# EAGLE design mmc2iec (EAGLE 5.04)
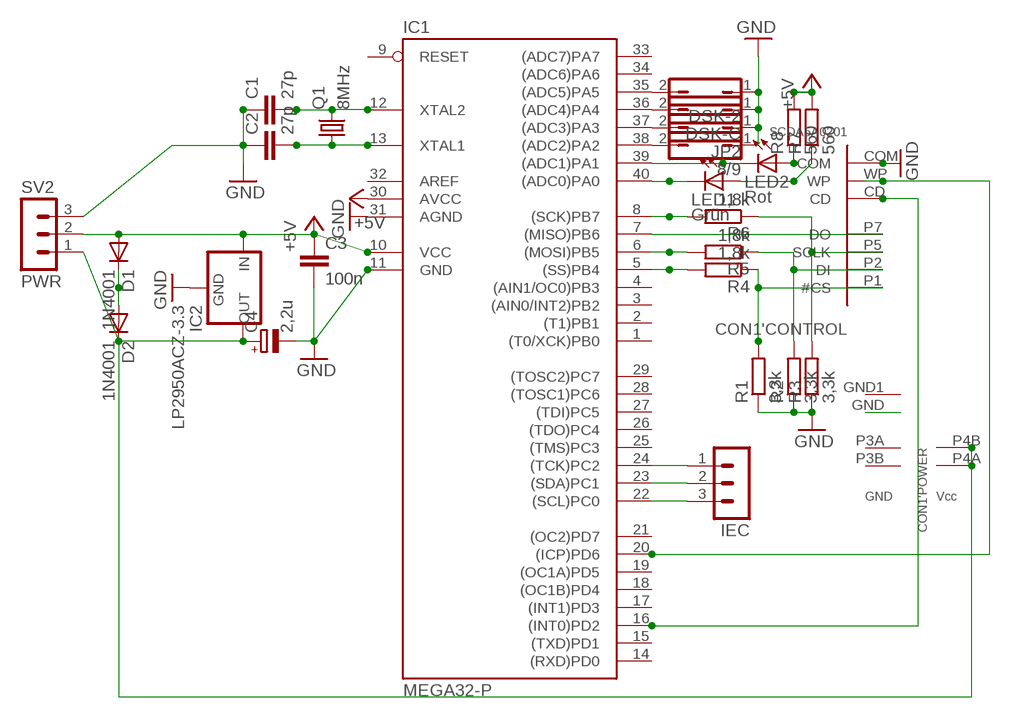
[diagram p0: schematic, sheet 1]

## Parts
8/9  JP1Q  [JP1]
C1  27p  C-EU025-025X050  [C025-025X050]
C2  27p  C-EU025-025X050  [C025-025X050]
C3  100n  C-EU025-025X050  [C025-025X050]
C4  2,2u  CPOL-EUE2.5-5  [E2,5-5]
CON1  SCDA5A0201  [SCDA5A0201]
D1  1N4001  1N4004  [DO41-10]
D2  1N4001  1N4004  [DO41-10]
DSK-2  JP1Q  [JP1]
DSK-C  JP1Q  [JP1]
IC1  MEGA32-P  [DIL40]
IC2  LP2950ACZ-3.3  [TO92]
IEC  MA03-1  [MA03-1]
JP2  JP1Q  [JP1]
LED1  Grün  LED3MM  [LED3MM]
LED2  Rot  LED3MM  [LED3MM]
Q1  8MHz  CRYSTALHC49U-V  [HC49U-V]
R1  3,3k  R-EU_0207/7  [0207/7]
R2  3,3k  R-EU_0207/7  [0207/7]
R3  3,3k  R-EU_0207/7  [0207/7]
R4  1,8k  R-EU_0207/7  [0207/7]
R5  1,8k  R-EU_0207/7  [0207/7]
R6  1,8k  R-EU_0207/7  [0207/7]
R7  560  R-EU_0207/7  [0207/7]
R8  560  R-EU_0207/7  [0207/7]
SV2  PWR  MA03-1  [MA03-1]

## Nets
+5V: C3.1 D1.A IC1.10(VCC) IC1.30(AVCC) IC2.3(IN) R7.2 R8.2 SV2.2
GND: 8/9.1 C1.1 C2.1 C3.2 C4.- CON1.COM('CONTROL:COM) DSK-2.1 DSK-C.1 IC1.11(GND) IC1.31(AGND) IC2.2(GND) JP2.1 R1.1 R2.1 R3.1 SV2.3
N$1: C1.2 IC1.12(XTAL2) Q1.2
N$2: C2.2 IC1.13(XTAL1) Q1.1
N$3: 8/9.2 IC1.38((ADC2)PA2)
N$4: IC1.5((SS)PB4) R4.2
N$5: IC1.6((MOSI)PB5) R5.2
N$6: IC1.8((SCK)PB7) R6.2
N$7: CON1.P1('CONTROL:#CS) R1.2 R4.1
N$8: CON1.P7('CONTROL:DO) IC1.7((MISO)PB6)
N$9: CON1.P2('CONTROL:DI) R2.2 R5.1
N$10: IC1.40((ADC0)PA0) LED1.K(C)
N$11: IC1.39((ADC1)PA1) LED2.K(C)
N$12: LED1.A R7.1
N$13: LED2.A R8.1
N$14: IC1.37((ADC3)PA3) JP2.2
N$15: C4.+ CON1.P4A('POWER:VCC) CON1.P4B('POWER:VCC1) D2.C IC2.1(OUT) SV2.1
N$16: D1.C D2.A
N$17: IC1.22((SCL)PC0) IEC.3
N$18: IC1.23((SDA)PC1) IEC.2
N$19: IC1.24((TCK)PC2) IEC.1
N$20: CON1.P5('CONTROL:SCLK) R3.2 R6.1
N$22: DSK-C.2 IC1.36((ADC4)PA4)
N$23: CON1.CD('CONTROL:CD) IC1.16((INT0)PD2)
N$24: CON1.WP('CONTROL:WP) IC1.20((ICP)PD6)
N$25: DSK-2.2 IC1.35((ADC5)PA5)
Unconnected: IC1.1((T0/XCK)PB0) IC1.2((T1)PB1) IC1.3((AIN0/INT2)PB2) IC1.4((AIN1/OC0)PB3) IC1.9(RESET) IC1.14((RXD)PD0) IC1.15((TXD)PD1) IC1.17((INT1)PD3) IC1.18((OC1B)PD4) IC1.19((OC1A)PD5) IC1.21((OC2)PD7) IC1.25((TMS)PC3) IC1.26((TDO)PC4) IC1.27((TDI)PC5) IC1.28((TOSC1)PC6) IC1.29((TOSC2)PC7) IC1.32(AREF) IC1.33((ADC7)PA7) IC1.34((ADC6)PA6)

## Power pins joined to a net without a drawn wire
GND: CON1.GND1('POWER:GND) CON1.GND('POWER:GND) CON1.P3A('POWER:GND) CON1.P3B('POWER:GND)

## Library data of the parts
8/9 DSK-2 DSK-C JP2 = jumper:JP1Q: JUMPER
C1-C3 = rcl:C-EU: CAPACITOR, European symbol
C4 = rcl:CPOL-EU: POLARIZED CAPACITOR, European symbol
CON1 = SCDA5A0201:SCDA5A0201: ALPS Connector for SDMemory Card SD-CARD SCDA5A0201 SPI -MODE
D1 D2 = diode:1N4004: DIODE
IC1 = atmel:MEGA32-P: MICROCONTROLLER 32 Kbytes FLASH 2 Kbytes SRAM 1 Kbytes EEPROM USART 8-channel 10 bit ADC Source: www.atmel.com .. doc2503.pdf
IC2 = v-reg:LP2950?*: Source: http://cache.national.com/ds/LP/LP2950.pdf
IEC SV2 = con-lstb:MA03-1: PIN HEADER
LED1 LED2 = led:LED: LED
Q1 = crystal:CRYSTAL: CRYSTAL
R1-R8 = rcl:R-EU_: RESISTOR, European symbol

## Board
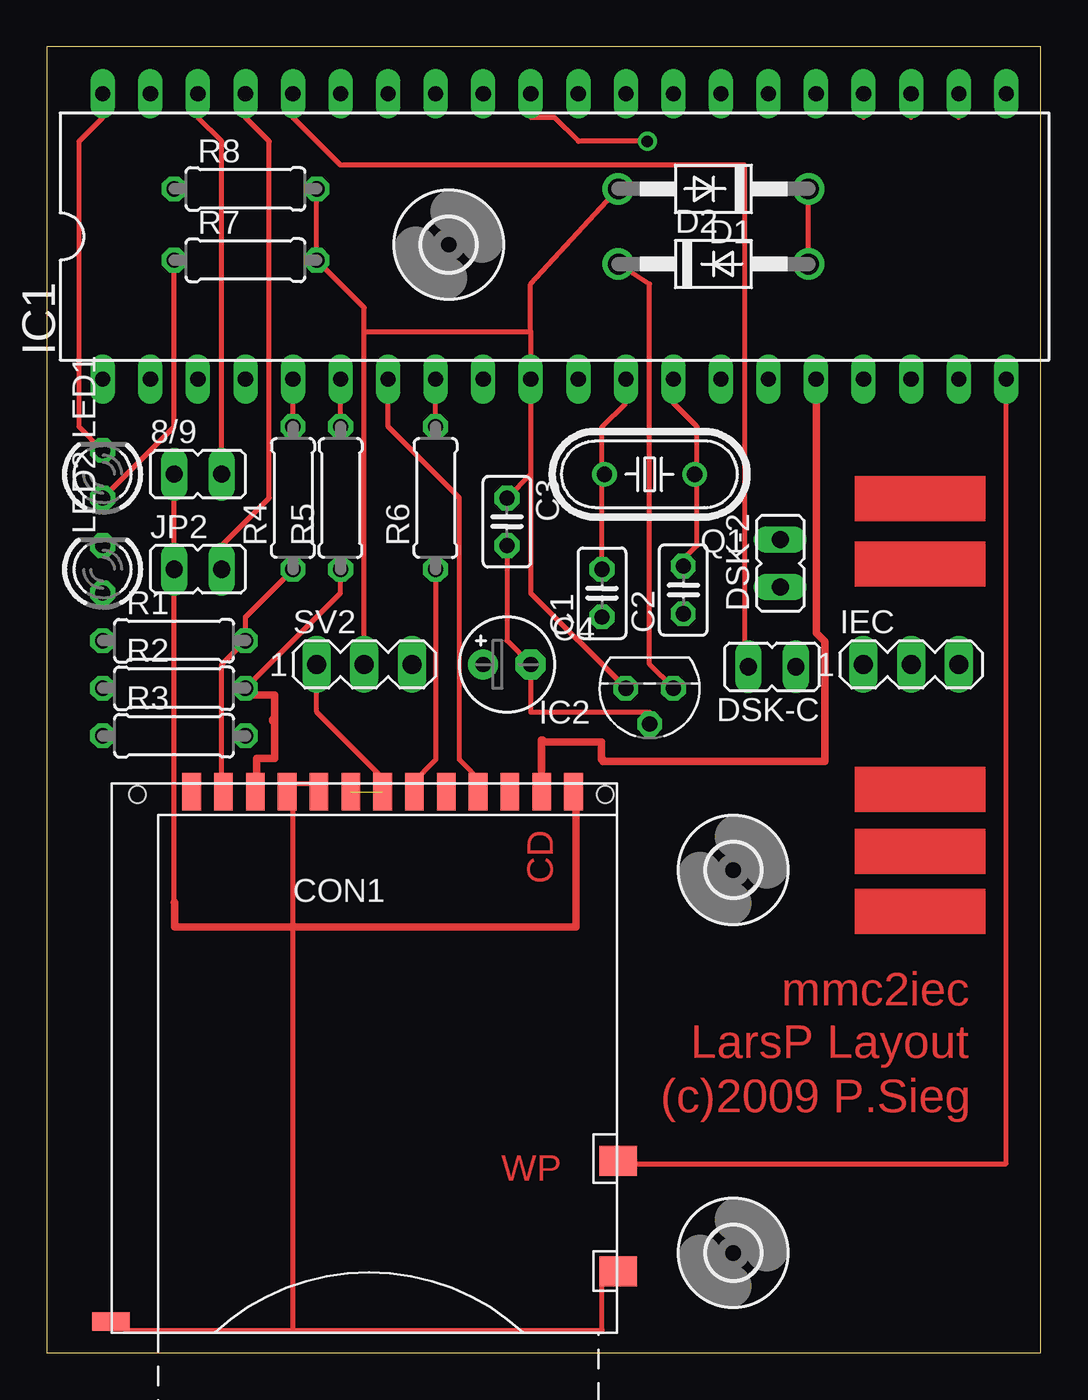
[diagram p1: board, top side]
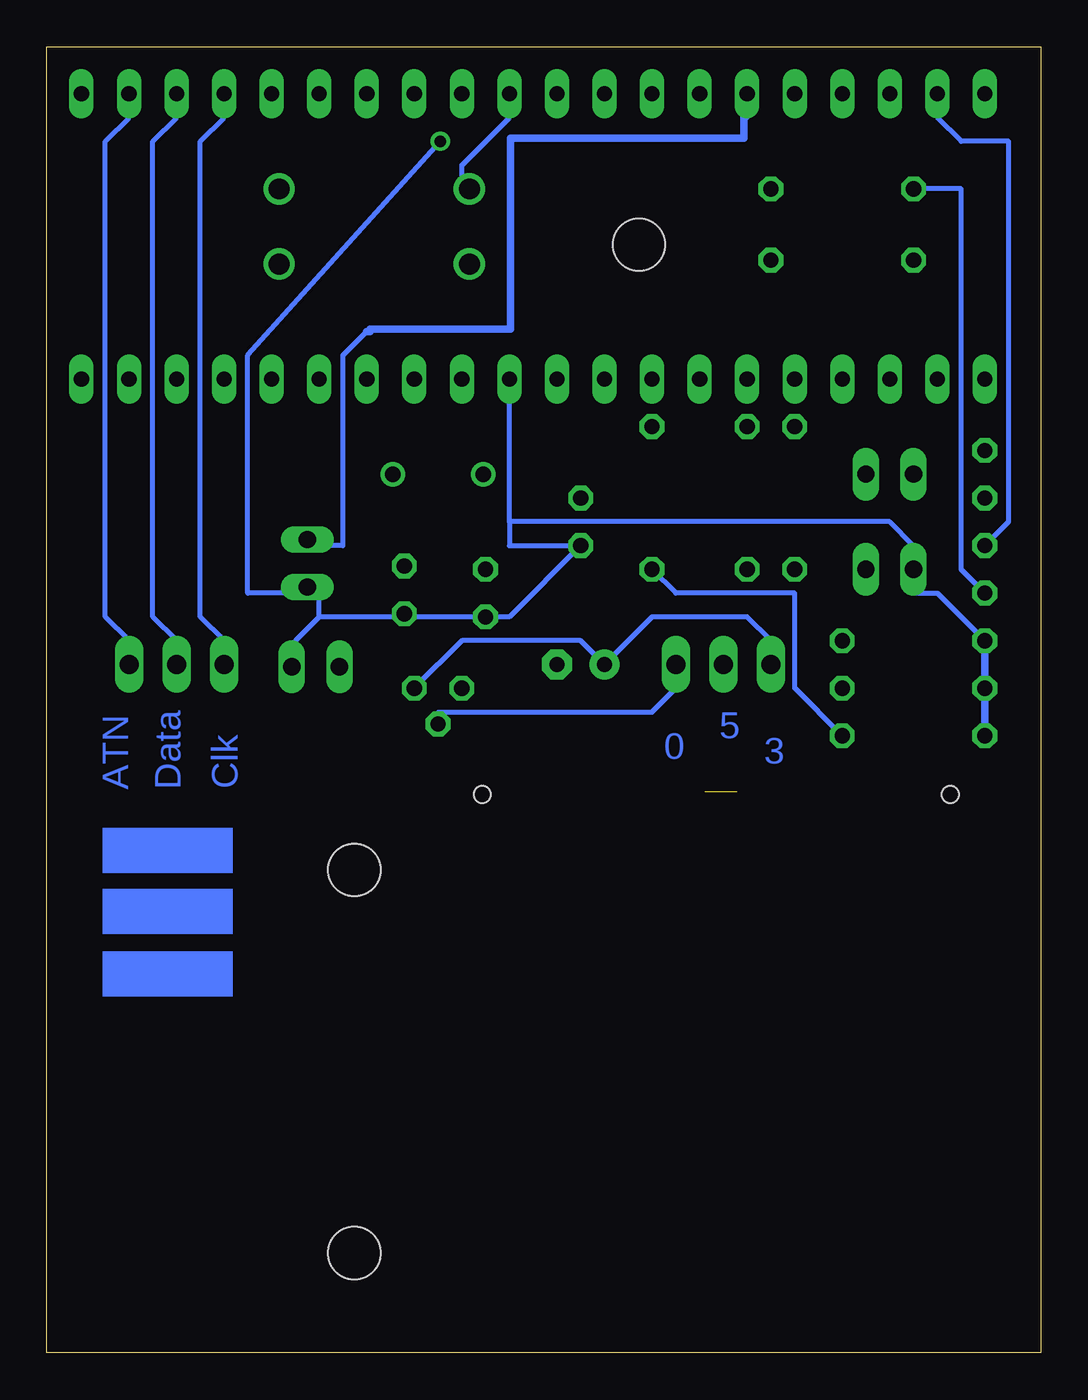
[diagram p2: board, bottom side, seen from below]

Size 53.1 x 69.75 mm. Coordinates in mm from the lower left corner, seen from the top.
Outline: 0,0 53.1,0 53.1,69.75 0,69.75 0,0
Copper layers (1*16): Top 0.035mm / dielectric 1.5mm / Bottom 0.035mm
Design rules "default": minimum track width 10mil, minimum drill 24mil, track to track 8mil, track to pad 8mil, pad to pad 8mil, via to via 8mil, smd to smd 8mil, copper to edge 40mil, drill to drill 8mil, minimum pad ring 10mil, minimum via ring 8mil, stop-mask expansion 4mil, vias tented up to drill 0mil, thermal gap 10mil

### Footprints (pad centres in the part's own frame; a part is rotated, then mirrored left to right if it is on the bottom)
JP1 = drill 0.914 long: 1 0,-1.27; 2 0,1.27
C025-025X050 = drill 0.813 octagon: 1 -1.27,0; 2 1.27,0
E2,5-5 = drill 0.813 pad 1.6 round: + -1.27,0 | drill 0.813 pad 1.6 octagon: - 1.27,0
SCDA5A0201 = smd 1 x 2: CD 9.475,-0.45; COM 11.175,-0.45; P1 -7.525,-0.45; P2 -5.825,-0.45; P3A -4.125,-0.45; P3B -2.425,-0.45; P4A -0.725,-0.45; P4B 0.975,-0.45; P5 2.675,-0.45; P6 4.375,-0.45; P7 6.075,-0.45; P8 7.775,-0.45; P9 -9.225,-0.45 | smd 2 x 1.6: GND 13.575,-26.05; WP 13.575,-20.15 | smd 2 x 1: GND1 -13.525,-28.75 | hole 0.9: -12.125,-0.6; 12.875,-0.6
DO41-10 = drill 1.118 round: A 5.08,0; C -5.08,0
DIL40 = drill 0.813 long: 1 -24.13,-7.62; 2 -21.59,-7.62; 3 -19.05,-7.62; 4 -16.51,-7.62; 5 -13.97,-7.62; 6 -11.43,-7.62; 7 -8.89,-7.62; 8 -6.35,-7.62; 9 -3.81,-7.62; 10 -1.27,-7.62; 11 1.27,-7.62; 12 3.81,-7.62; 13 6.35,-7.62; 14 8.89,-7.62; 15 11.43,-7.62; 16 13.97,-7.62; 17 16.51,-7.62; 18 19.05,-7.62; 19 21.59,-7.62; 20 24.13,-7.62; 21 24.13,7.62; 22 21.59,7.62; 23 19.05,7.62; 24 16.51,7.62; 25 13.97,7.62; 26 11.43,7.62; 27 8.89,7.62; 28 6.35,7.62; 29 3.81,7.62; 30 1.27,7.62; 31 -1.27,7.62; 32 -3.81,7.62; 33 -6.35,7.62; 34 -8.89,7.62; 35 -11.43,7.62; 36 -13.97,7.62; 37 -16.51,7.62; 38 -19.05,7.62; 39 -21.59,7.62; 40 -24.13,7.62
TO92 = drill 0.813 octagon: 1 -1.27,0; 2 0,1.905; 3 1.27,0
MA03-1 = drill 1.016 long: 1 -2.54,0; 2 0,0; 3 2.54,0
LED3MM = drill 0.813 octagon: A -1.27,0; K 1.27,0
HC49U-V = drill 0.813 round: 1 -2.413,0; 2 2.413,0
0207/7 = drill 0.813 octagon: 1 -3.81,0; 2 3.81,0
2,8 = hole 2.8: 0,0

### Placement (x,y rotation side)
8/9  8.07,46.92 270 top
C1  29.66,40.57 90 top
C2  34,40.74 90 top
C3  24.58,44.38 270 top
C4  24.58,36.76 0 top
CON1  16.96,30.41 0 top
D1  35.61,62.16 180 top
D2  35.61,58.15 0 top
DSK-2  39.18,42.16 0 top
DSK-C  38.74,36.64 90 top
IC1  27.12,59.62 0 top
IC2  32.2,35.49 180 top
IEC  46.17,36.76 0 top
JP2  8.07,41.84 270 top
LED1  2.99,46.92 90 top
LED2  2.99,41.84 90 top
Q1  32.2,46.92 180 top
R1  6.8,38.03 0 top
R2  6.8,35.49 0 top
R3  6.8,32.95 0 top
R4  13.15,45.65 90 top
R5  15.69,45.65 90 top
R6  20.77,45.65 90 top
R7  10.61,58.35 0 top
R8  10.61,62.16 0 top
SV2  16.96,36.76 0 top
U$1  [2,8]  36.67,25.78 0 top
U$2  [2,8]  21.47,59.18 0 top
U$3  [2,8]  36.67,5.33 0 top

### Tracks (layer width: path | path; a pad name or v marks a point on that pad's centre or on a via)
+5V
  Top 0.254: R8.2 R7.2 16.96,55.81 16.96,54.54 | SV2.2 16.96,54.54 | 25.85,46.92 C3.1 | 25.85,46.92 IC1.10 25.85,54.54 | IC2.3 25.85,40.57 25.85,46.92 | D1.A 25.85,57.08 25.85,54.54 | 16.96,54.54 25.85,54.54
  Bottom 0.254: IC1.30 28.39,65.97 30.93,63.43 30.93,62.16 D1.A
GND  (via drill 0.61)
  Top 0.254: CON1.P3B 14.42,30.41 13.15,30.41 CON1.P3A 13.15,29.14 13.15,22.73 13.15,1.2 | 13.15,1.2 29.66,1.2 29.66,3.74 CON1.GND | 13.15,1.2 4.26,1.2 CON1.GND1 | 8/9.1 JP2.1 6.8,24.06 | IC2.2 32.2,34.22 25.85,34.22 C4.- 24.58,38.03 C3.2 | v32.08,64.7 28.39,64.7 27.12,65.97 25.85,65.97 IC1.31
  Top 0.406: CON1.COM 28.27,29.96 28.27,22.73 13.15,22.73 6.82,22.73 6.82,24.06 6.8,24.06
  Bottom 0.254: R1.1 5.53,40.57 6.8,40.57 JP2.1 6.8,43.11 8.07,44.38 28.39,44.38 | SV2.3 19.5,35.49 20.77,34.22 32.2,34.22 IC2.2 | 28.39,44.38 28.39,43.11 C3.2 28.39,39.3 C1.1 33.47,39.3 | 28.39,44.38 IC1.11 | 38.55,39.3 39.82,38.03 DSK-C.1 | 33.47,39.3 38.55,39.3 | 33.47,39.3 C2.1 | 38.55,39.3 38.55,40.57 DSK-2.1 39.82,40.57 42.36,40.57 42.36,53.27 v32.08,64.7
  Bottom 0.406: R1.1 R2.1 2.99,32.53 3.02,32.53 3.02,32.83 | R3.1 3.02,32.95 3.02,32.83 | 3.02,32.73 3.02,32.83
N$1
  Top 0.254: C1.2 29.66,46.92 | 29.66,46.92 29.66,49.46 30.93,50.73 IC1.12 | 29.66,46.92 Q1.2
N$2
  Top 0.254: 34.74,46.92 34.74,49.46 33.47,50.73 IC1.13 | 34.74,46.92 34.74,43.11 33.47,41.84 C2.2 | 34.74,46.92 Q1.1
N$3
  Top 0.254: IC1.38 8.07,65.97 9.34,64.7 8/9.2
N$4
  Top 0.254: R4.2 IC1.5
N$5
  Top 0.254: R5.2 IC1.6
N$6
  Top 0.254: R6.2 IC1.8
N$7
  Top 0.254: CON1.P1 9.34,30.41 9.34,36.76 R1.2 10.61,39.3 R4.1
N$8
  Top 0.254: CON1.P7 23.31,30.41 22.04,31.68 22.04,45.65 18.23,49.46 IC1.7
N$9
  Top 0.254: R2.2 15.69,40.57 R5.1
  Top 0.406: 11.07,29.96 CON1.P2 11.22,29.96 11.22,31.73 12.17,31.73 12.17,33.28 | R2.2 10.77,35.49 10.77,35.13 12.17,35.13 12.17,33.28 | 12.07,33.83 12.07,33.73 12.17,33.73 12.17,33.28
N$10
  Top 0.254: LED1.K 1.72,49.46 1.72,64.7 2.99,65.97 IC1.40
N$11
  Bottom 0.254: LED2.K 1.72,44.38 1.72,64.7 4.26,64.7 5.53,65.97 IC1.39
N$12
  Top 0.254: LED1.A 6.8,49.46 R7.1
N$13
  Bottom 0.254: LED2.A 4.26,41.84 4.26,62.16 R8.1
N$14
  Top 0.254: IC1.37 10.61,65.97 11.88,64.7 11.88,45.65 9.34,43.11 JP2.2
N$15  (1 unrouted)
  Top 0.254: CON1.P4B 18.23,30.41 14.42,34.22 SV2.1 | D2.C 32.2,57.08 32.2,36.76 IC2.1
  Bottom 0.254: IC2.1 30.93,38.03 24.58,38.03 C4.+ 20.77,39.3 15.69,39.3 14.42,38.03 SV2.1
N$16
  Top 0.254: D2.A D1.C
N$17
  Top 0.254: IC1.22 48.71,65.97 | IEC.3 48.71,38.03
  Bottom 0.254: IC1.22 48.71,65.97 49.98,64.7 49.98,39.3 48.71,38.03 IEC.3
N$18
  Top 0.254: IC1.23 46.17,65.97 | IEC.2 46.17,38.03
  Bottom 0.254: IC1.23 46.17,65.97 47.44,64.7 47.44,39.3 46.17,38.03 IEC.2
N$19
  Top 0.254: IC1.24 43.63,65.97 | IEC.1 43.63,38.03
  Bottom 0.254: IC1.24 43.63,65.97 44.9,64.7 44.9,39.3 43.63,38.03 IEC.1
N$20
  Top 0.254: R6.1 20.77,31.68 19.5,30.41 CON1.P5
  Bottom 0.254: R3.2 13.15,35.49 13.15,40.57 19.5,40.57 R6.1
N$22
  Top 0.254: IC1.36 13.15,65.97 15.69,63.43 37.28,63.43 37.28,38.03 DSK-C.2
N$23
  Top 0.406: 41.12,51.78 41.02,51.88 41.09,51.95 IC1.16 41.04,52 41.02,51.98 41.12,51.88 41.12,38.43 41.57,37.98 41.57,31.58 29.72,31.58 29.72,31.68 29.62,31.68 29.62,32.63 26.47,32.63 26.47,32.73 26.44,32.73 CON1.CD
  Bottom 0.406: IC1.16 41.12,52
N$24
  Top 0.254: CON1.WP 30.93,10.09 51.25,10.09 IC1.20
N$25
  Bottom 0.254: 36.01,54.54 37.28,53.27 37.28,43.11 38.55,43.11 DSK-2.2 | IC1.35 15.69,65.97
  Bottom 0.406: 36.01,54.54 35.82,54.54 35.82,54.68 28.32,54.68 28.32,64.88 15.87,64.88 15.87,67.24 IC1.35
(copper drawn outside any net)
  shapes: Bottom area x3, Top area x5

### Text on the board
Top: CD | mmc2iec | LarsP Layout | (c)2009 P.Sieg | WP
Bottom: 5 | Data | 0 | ATN | 3 | Clk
